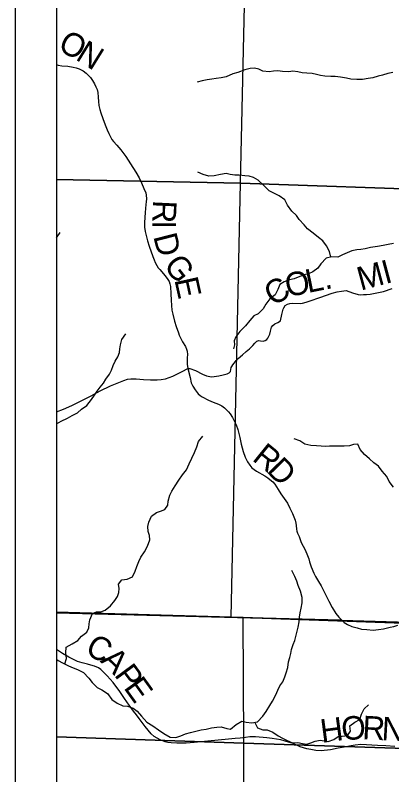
# Model space of a CAD drawing. Extents: x 0 to 34, y 0 to 22.
# Drawn here: x 2 to 2.91, y 18.326 to 20.162 of the extents above; entities that cross this region are included whole.
import ezdxf

# ---------------------------------------------------------------- set-up
doc = ezdxf.new("R2010")
doc.units = 0
for name, color, linetype in [('Default', 7, 'Continuous'), ('GM_X_County_Road', 7, 'Continuous'), ('GM_X_County_Road_Text', 7, 'Continuous'), ('GM_X_Minor_River', 7, 'Continuous'), ('GM_X_Rail_Line', 7, 'Continuous'), ('GM_X_Section', 7, 'Continuous'), ('GM_X_Township_Road', 7, 'Continuous'), ('GM_X_Township_Road_Text', 7, 'Continuous'), ('SH_Cut_Line', 7, 'Continuous'), ('SH_Data', 7, 'Continuous')]:
    doc.layers.add(name, color=color, linetype=linetype)

msp = doc.modelspace()

# ---------------------------------------------------------------- linework, layer by layer
at = {"layer": 'Default'}
for points in [[(2.1, 20.7777), (2.1, 19.7647), (2.5439, 19.7556), (2.5664, 20.7581)], [(2.1, 19.7647), (2.1, 18.7189), (2.5214, 18.7068), (2.5439, 19.7556)], [(2.1, 18.7189), (2.1, 18.418), (2.5522, 18.4023), (2.551, 18.706), (2.5214, 18.7068)], [(2.1, 18.418), (2.1, 17.4114), (2.5532, 17.3998), (2.5522, 18.4023)]]:
    msp.add_lwpolyline(points, close=True, dxfattribs=at)
at = {"layer": 'GM_X_County_Road'}
msp.add_lwpolyline([(2.9169, 18.3941), (2.8954, 18.3961), (2.8751, 18.3972), (2.8344, 18.399), (2.8213, 18.3978), (2.8112, 18.3959), (2.7948, 18.3926), (2.7799, 18.39), (2.7618, 18.3863), (2.7392, 18.3841), (2.7261, 18.3847), (2.7142, 18.3868), (2.7047, 18.3888), (2.6881, 18.3937), (2.6711, 18.4017), (2.652, 18.4071), (2.6412, 18.4102), (2.6311, 18.4122), (2.6203, 18.4141), (2.6077, 18.4157), (2.5804, 18.4178), (2.5671, 18.4178), (2.5561, 18.4162), (2.5435, 18.4145), (2.5311, 18.4134), (2.5154, 18.4121), (2.4653, 18.4076), (2.4322, 18.4043), (2.4128, 18.4023), (2.3905, 18.4023), (2.377, 18.403), (2.3688, 18.4042), (2.3623, 18.4059), (2.3505, 18.4103), (2.3428, 18.4142), (2.3355, 18.4189), (2.3283, 18.4252), (2.3213, 18.4337), (2.3136, 18.4429), (2.2991, 18.4622), (2.2927, 18.471), (2.286, 18.4798), (2.2752, 18.4943), (2.2636, 18.5108), (2.2525, 18.5272), (2.2365, 18.5492), (2.2224, 18.5654), (2.2152, 18.5727), (2.207, 18.5801), (2.2008, 18.5843), (2.1915, 18.5884), (2.183, 18.5909), (2.1747, 18.5931), (2.1621, 18.5962), (2.1505, 18.5999), (2.1292, 18.6105), (2.1141, 18.6193), (2.1018, 18.6275), (2.1, 18.6286)], dxfattribs=at)
at = {"layer": 'GM_X_Minor_River'}
for points in [[(2.912, 20.0233), (2.9002, 20.0205), (2.887, 20.017), (2.8765, 20.0139), (2.864, 20.0104), (2.8527, 20.0084), (2.8387, 20.0064), (2.8254, 20.0059), (2.8107, 20.0073), (2.8004, 20.0098), (2.786, 20.012), (2.7731, 20.0138), (2.7625, 20.0133), (2.7478, 20.0139), (2.7372, 20.0161), (2.7277, 20.0179), (2.7174, 20.0205), (2.7046, 20.0215), (2.6928, 20.0226), (2.683, 20.0244), (2.6708, 20.0262), (2.661, 20.0246), (2.6458, 20.0259), (2.6341, 20.027), (2.6239, 20.0265), (2.6137, 20.0249), (2.5985, 20.0263), (2.5883, 20.0315), (2.5776, 20.0337), (2.5674, 20.0328), (2.5546, 20.0293), (2.538, 20.0235), (2.5255, 20.0196), (2.5093, 20.0126), (2.4972, 20.0099), (2.4851, 20.0086), (2.4753, 20.007), (2.464, 20.0054), (2.4515, 20.003), (2.4398, 19.9999)], [(2.7623, 19.577), (2.7591, 19.5908), (2.7522, 19.604), (2.743, 19.6165), (2.7327, 19.6247), (2.7193, 19.6349), (2.7056, 19.6454), (2.698, 19.6551), (2.6861, 19.6676), (2.6792, 19.6774), (2.6678, 19.6879), (2.6574, 19.7022), (2.6509, 19.7158), (2.6379, 19.7248), (2.6261, 19.7307), (2.6132, 19.7371), (2.6006, 19.7499), (2.5869, 19.763), (2.5758, 19.769), (2.5652, 19.7727), (2.5546, 19.7737), (2.5406, 19.7748), (2.5307, 19.775), (2.5194, 19.7765), (2.5099, 19.7787), (2.4955, 19.777), (2.4808, 19.7731), (2.4675, 19.7726), (2.4543, 19.7763), (2.4413, 19.7822)], [(2.1, 19.6236), (2.1013, 19.6257), (2.1084, 19.6368)], [(2.9137, 19.6096), (2.9009, 19.6076), (2.8884, 19.6048), (2.8748, 19.6025), (2.8585, 19.6), (2.8453, 19.5973), (2.8351, 19.5957), (2.8253, 19.5944), (2.8132, 19.5924), (2.8019, 19.5874), (2.7909, 19.5828), (2.7789, 19.577), (2.7649, 19.5776), (2.7513, 19.5745), (2.7385, 19.5607), (2.7307, 19.5504), (2.719, 19.5416), (2.7081, 19.5362), (2.6979, 19.5338), (2.6873, 19.5299), (2.6737, 19.5249), (2.6628, 19.5221), (2.6496, 19.5171), (2.6394, 19.5106), (2.6342, 19.4991), (2.6275, 19.4862), (2.6151, 19.4762), (2.6054, 19.4636), (2.5987, 19.4522), (2.5871, 19.44), (2.5765, 19.4353), (2.5664, 19.4242), (2.5559, 19.4113), (2.5424, 19.3975), (2.5327, 19.3845), (2.529, 19.3746), (2.5298, 19.3652), (2.5269, 19.3557)], [(2.1, 19.1743), (2.1109, 19.1803), (2.126, 19.1877), (2.1377, 19.1942), (2.1501, 19.2011), (2.1599, 19.2092), (2.173, 19.2188), (2.1839, 19.2333), (2.1914, 19.2432), (2.1977, 19.2527), (2.2056, 19.2627), (2.2135, 19.2722), (2.219, 19.2821), (2.228, 19.2939), (2.2325, 19.3042), (2.2365, 19.3152), (2.2417, 19.3255), (2.2477, 19.3362), (2.2518, 19.3461), (2.2528, 19.3556), (2.2546, 19.3651), (2.2579, 19.3776), (2.2669, 19.3917)], [(2.1198, 18.5938), (2.1239, 18.6069), (2.1223, 18.6205), (2.1233, 18.6346), (2.1373, 18.6423), (2.1516, 18.6507), (2.1602, 18.661), (2.1733, 18.671), (2.1782, 18.6813), (2.1788, 18.6908), (2.1803, 18.7006), (2.1866, 18.7162), (2.1964, 18.7201), (2.207, 18.7202), (2.2172, 18.7241), (2.2299, 18.7344), (2.2408, 18.7474), (2.2468, 18.7569), (2.2505, 18.7664), (2.2515, 18.7763), (2.2492, 18.7869), (2.2578, 18.7972), (2.2703, 18.7984), (2.2834, 18.8042), (2.2894, 18.8183), (2.2934, 18.829), (2.299, 18.8412), (2.3031, 18.8518), (2.3124, 18.8652), (2.3199, 18.8789), (2.3254, 18.8941), (2.3242, 18.9039), (2.3215, 18.9138), (2.3202, 18.9262), (2.3224, 18.9369), (2.3291, 18.951), (2.3411, 18.9598), (2.3509, 18.9629), (2.3615, 18.9668), (2.369, 18.9778), (2.3696, 18.9873), (2.3737, 19.0014), (2.3785, 19.0113), (2.3863, 19.0242), (2.3949, 19.0383), (2.4043, 19.0509), (2.4136, 19.0632), (2.4203, 19.0776), (2.4263, 19.0913), (2.4329, 19.105), (2.4385, 19.1183), (2.4429, 19.1316), (2.453, 19.1442)], [(2.914, 19.0208), (2.9033, 19.0344), (2.8975, 19.0472), (2.8864, 19.0597), (2.8776, 19.0721), (2.8662, 19.0799), (2.8559, 19.0893), (2.8433, 19.1002), (2.833, 19.1123), (2.8272, 19.1247), (2.817, 19.1239), (2.8071, 19.1208), (2.7947, 19.1199), (2.7822, 19.1198), (2.772, 19.1205), (2.7595, 19.1203), (2.7493, 19.1191), (2.7386, 19.1198), (2.7277, 19.1208), (2.7137, 19.1215), (2.6996, 19.1248), (2.6871, 19.1334), (2.6738, 19.1382)], [(2.4363, 18.4314), (2.4491, 18.4346), (2.4616, 18.4366), (2.474, 18.4393), (2.4869, 18.4413), (2.4975, 18.4422), (2.5108, 18.4381), (2.5202, 18.4363), (2.5334, 18.4474), (2.5477, 18.4559), (2.5576, 18.4529), (2.5712, 18.4515), (2.5852, 18.4539), (2.5979, 18.4677), (2.6065, 18.4791), (2.6147, 18.4936), (2.6218, 18.5043), (2.6296, 18.5191), (2.6345, 18.5309), (2.6393, 18.5408), (2.6464, 18.5507), (2.6512, 18.5625), (2.6545, 18.5728), (2.6586, 18.5857), (2.6604, 18.599), (2.6633, 18.6097), (2.6659, 18.6195), (2.6677, 18.629), (2.6717, 18.6408), (2.6754, 18.6503), (2.678, 18.6602), (2.6813, 18.6731), (2.6835, 18.683), (2.6856, 18.6959), (2.687, 18.7073), (2.6885, 18.7171), (2.6906, 18.7285), (2.6928, 18.7414), (2.6934, 18.7543), (2.6891, 18.7695), (2.6833, 18.7831), (2.6806, 18.794), (2.6752, 18.8054), (2.6683, 18.8197)], [(2.1, 18.6053), (2.1039, 18.6022), (2.1142, 18.5966), (2.1286, 18.5895), (2.1404, 18.5843), (2.1507, 18.5806), (2.1651, 18.5731), (2.1781, 18.5592), (2.1858, 18.5494), (2.198, 18.537), (2.209, 18.531), (2.2231, 18.5225), (2.2335, 18.5081), (2.246, 18.4988), (2.2601, 18.4928), (2.2711, 18.4922), (2.2847, 18.4874), (2.2943, 18.4802), (2.3054, 18.4674), (2.3183, 18.4531), (2.3324, 18.4446), (2.3458, 18.4348), (2.3587, 18.4258), (2.3739, 18.4172), (2.3883, 18.4162), (2.4, 18.4201), (2.4117, 18.4248), (2.423, 18.4279), (2.4363, 18.4314)], [(2.5785, 18.4528), (2.5853, 18.4395), (2.5982, 18.4343), (2.6084, 18.4348), (2.6221, 18.4292), (2.6351, 18.4199), (2.6453, 18.4143), (2.6552, 18.4094), (2.67, 18.4035), (2.6825, 18.404), (2.6943, 18.4018), (2.7045, 18.4004), (2.7143, 18.4035), (2.7241, 18.4074), (2.7362, 18.4094), (2.7461, 18.4083), (2.7555, 18.4069), (2.7699, 18.4112), (2.7797, 18.4185), (2.7895, 18.4193), (2.8027, 18.4213), (2.8102, 18.4316), (2.8082, 18.4441), (2.8202, 18.4533), (2.8327, 18.4599), (2.8367, 18.4724), (2.843, 18.4854), (2.8536, 18.4953)]]:
    msp.add_lwpolyline(points, dxfattribs=at)
at = {"layer": 'GM_X_Rail_Line'}
for points in [[(4.5874, 20.9), (2.1, 20.9), (2.1, 18.7171), (2.7864, 18.6994), (2.7892, 18.6993), (2.9222, 18.6946), (2.9234, 18.6945), (3.8442, 18.6615), (3.8456, 18.6615), (4.5462, 18.6416), (4.5515, 18.7621), (4.5519, 18.771), (4.5566, 18.8683), (4.5569, 18.8737), (4.5569, 18.8748), (4.5571, 18.8875), (4.5772, 20.3136), (4.5773, 20.3149)], [(2.1, 18.7171), (2.1, 14.1), (4.5781, 14.1), (4.5658, 14.9668), (4.5509, 15.5331), (4.5478, 16.582), (4.5489, 17.6578), (4.5474, 17.7028), (4.5429, 17.9404), (4.5419, 17.9684), (4.5402, 18.2851), (4.5408, 18.3763), (4.5397, 18.3961), (4.5397, 18.4045), (4.5399, 18.4424), (4.5403, 18.5054), (4.5462, 18.6416), (3.8456, 18.6615), (3.8442, 18.6615), (2.9234, 18.6945), (2.9222, 18.6946), (2.7892, 18.6993), (2.7864, 18.6994)]]:
    msp.add_lwpolyline(points, close=True, dxfattribs=at)
at = {"layer": 'GM_X_Section'}
for points in [[(2.5664, 20.7581), (3.5738, 20.7275), (3.5637, 19.7201), (2.5439, 19.7556)], [(2.5439, 19.7556), (3.5637, 19.7201), (3.5541, 18.6711), (2.551, 18.706), (2.5214, 18.7068)], [(2.551, 18.706), (3.5541, 18.6711), (3.5508, 18.3698), (2.5522, 18.4023)], [(2.5522, 18.4023), (3.5508, 18.3698), (3.5573, 17.3676), (2.5532, 17.3998)]]:
    msp.add_lwpolyline(points, close=True, dxfattribs=at)
at = {"layer": 'GM_X_Township_Road'}
for points in [[(2.1, 20.0421), (2.1041, 20.0411), (2.1126, 20.0396), (2.1268, 20.0382), (2.1398, 20.0362), (2.1469, 20.0347), (2.1548, 20.0318), (2.1644, 20.0268), (2.1717, 20.0212), (2.1774, 20.0159), (2.1821, 20.0107), (2.1871, 20.0034), (2.1916, 19.9955), (2.1951, 19.9882), (2.1976, 19.9818), (2.1996, 19.9745), (2.2006, 19.9634), (2.2014, 19.9528), (2.202, 19.9435), (2.2044, 19.9337), (2.2068, 19.9254), (2.2116, 19.9119), (2.2172, 19.8963), (2.2218, 19.8846), (2.2258, 19.8758), (2.2298, 19.868), (2.2336, 19.8616), (2.2377, 19.8565), (2.2455, 19.8472), (2.2548, 19.8364), (2.2674, 19.8203), (2.2782, 19.8025), (2.2911, 19.7821), (2.2993, 19.7684), (2.3049, 19.7564), (2.3109, 19.7429), (2.3152, 19.7322), (2.3164, 19.7266), (2.3168, 19.7179), (2.3167, 19.7109), (2.3158, 19.7039), (2.3138, 19.6845), (2.3122, 19.6605), (2.312, 19.6496), (2.3136, 19.6387), (2.3168, 19.6259), (2.3193, 19.6166), (2.3234, 19.6037), (2.3323, 19.5783), (2.3355, 19.5703), (2.3383, 19.5641), (2.342, 19.5564), (2.3453, 19.5513), (2.349, 19.5469), (2.3621, 19.5317), (2.3685, 19.5232), (2.3718, 19.5178), (2.3736, 19.5126), (2.3752, 19.5058), (2.3759, 19.4884), (2.3765, 19.4726), (2.3773, 19.4602), (2.3786, 19.4486), (2.3806, 19.439), (2.385, 19.4223), (2.3887, 19.4091), (2.3941, 19.3939), (2.3962, 19.3885), (2.3985, 19.3835), (2.4042, 19.3726), (2.411, 19.3611), (2.414, 19.3545), (2.4154, 19.3496), (2.416, 19.342), (2.4157, 19.3335), (2.4156, 19.3183), (2.4171, 19.3075), (2.4223, 19.2863), (2.4252, 19.2735), (2.4289, 19.2654), (2.4346, 19.2559), (2.4417, 19.2467), (2.4469, 19.2423), (2.4517, 19.2393), (2.4669, 19.2314), (2.4782, 19.2267), (2.4914, 19.2215), (2.4987, 19.2173), (2.5054, 19.2126), (2.5103, 19.2082), (2.5153, 19.2028), (2.5189, 19.1979), (2.5247, 19.1894), (2.5282, 19.1826), (2.5339, 19.1714), (2.5379, 19.1606), (2.5427, 19.1414), (2.5459, 19.1251), (2.5507, 19.107), (2.5557, 19.0937), (2.5614, 19.0822), (2.5666, 19.074), (2.5718, 19.068), (2.5771, 19.0635), (2.5829, 19.0599), (2.6027, 19.0482), (2.6099, 19.0439), (2.6153, 19.0399), (2.6223, 19.0337), (2.6271, 19.0282), (2.6348, 19.0154), (2.6414, 19.0053), (2.6576, 18.9828), (2.6637, 18.97), (2.6695, 18.9574), (2.6732, 18.9498), (2.6762, 18.9411), (2.6779, 18.9343), (2.6787, 18.9281), (2.6794, 18.9199), (2.6803, 18.915), (2.6819, 18.91), (2.6858, 18.9017), (2.691, 18.8876), (2.7001, 18.8699), (2.7063, 18.8557), (2.709, 18.8482), (2.7112, 18.8408), (2.7148, 18.8284), (2.7213, 18.813), (2.7255, 18.805), (2.7323, 18.7931), (2.7387, 18.7826), (2.7574, 18.7453), (2.7656, 18.7301), (2.7747, 18.7159), (2.7819, 18.7071), (2.7894, 18.6988), (2.7925, 18.6961)], [(2.1, 19.2035), (2.1163, 19.2096), (2.1365, 19.2182), (2.1832, 19.2418), (2.2054, 19.2541), (2.2305, 19.2659), (2.2625, 19.279), (2.2712, 19.2822), (2.2792, 19.2831), (2.2925, 19.2827), (2.3099, 19.281), (2.3271, 19.2803), (2.3428, 19.2808), (2.3524, 19.2814), (2.3628, 19.2832), (2.3807, 19.2894), (2.3953, 19.2967), (2.4035, 19.3008), (2.4171, 19.3075), (2.4194, 19.308), (2.422, 19.308), (2.4353, 19.3031), (2.4522, 19.2942), (2.462, 19.2905), (2.47, 19.2884), (2.4747, 19.2878), (2.4919, 19.2905), (2.5026, 19.2922), (2.5117, 19.2951), (2.5164, 19.2974), (2.5198, 19.3006), (2.522, 19.3099), (2.5231, 19.3129), (2.5255, 19.3169), (2.5286, 19.321), (2.5337, 19.3272), (2.5388, 19.3324), (2.5493, 19.3406), (2.5582, 19.349), (2.5655, 19.3557), (2.5742, 19.3636), (2.579, 19.3688), (2.5839, 19.3742), (2.5881, 19.3757), (2.5923, 19.375), (2.5986, 19.3737), (2.6035, 19.3756), (2.6076, 19.3783), (2.6101, 19.381), (2.6151, 19.3904), (2.6165, 19.3982), (2.6187, 19.4076), (2.6224, 19.4119), (2.6271, 19.4155), (2.6341, 19.4186), (2.6409, 19.4228), (2.6443, 19.4386), (2.6472, 19.451), (2.6491, 19.4543), (2.6524, 19.4602), (2.6579, 19.463), (2.6633, 19.4648), (2.6694, 19.4657), (2.688, 19.4651), (2.6942, 19.4656), (2.7027, 19.4681), (2.7127, 19.4717), (2.7354, 19.4794), (2.7655, 19.4896), (2.7779, 19.4928), (2.7883, 19.4945), (2.7997, 19.4962), (2.8143, 19.491), (2.8284, 19.4866), (2.8346, 19.4862), (2.8415, 19.4868), (2.8482, 19.4864), (2.8573, 19.4875), (2.8815, 19.4923), (2.8892, 19.4938), (2.9104, 19.5011)], [(2.7925, 18.6961), (2.7949, 18.6941), (2.8027, 18.6892), (2.8133, 18.6847), (2.8258, 18.6808), (2.8362, 18.6783), (2.8496, 18.6769), (2.8646, 18.6758), (2.8777, 18.6771), (2.8893, 18.6789), (2.9056, 18.6825), (2.9145, 18.6846), (2.9242, 18.6876)]]:
    msp.add_lwpolyline(points, dxfattribs=at)
at = {"layer": 'SH_Cut_Line'}
msp.add_lwpolyline([(8.9, 14.624), (8.9, 20.9), (2.1, 20.9), (2.1, 14.1)], dxfattribs=at)
at = {"layer": 'SH_Data'}
for p, q in [((2, 21), (2, 14)), ((2.1, 20.9), (2.1, 14.1))]:
    msp.add_line(p, q, dxfattribs=at)

# ---------------------------------------------------------------- texts
at = {"layer": 'GM_X_County_Road_Text'}
for s, rotation, p in [('C', 330.884, (2.166, 18.6205)), ('A', 315.7599, (2.2036, 18.6001)), ('P', 306.5192, (2.2378, 18.5671)), ('E', 305.7908, (2.2605, 18.5364)), ('O', 3.3314, (2.7892, 18.4094)), ('R', 356.9152, (2.8374, 18.4123)), ('N', 356.7709, (2.884, 18.4098)), ('H', 7.5222, (2.7407, 18.403))]:
    msp.add_text(s, height=0.0568, rotation=rotation, dxfattribs=at).set_placement(p)
at = {"layer": 'GM_X_Township_Road_Text'}
for s, rotation, p in [('O', 331.302, (2.1004, 20.0791)), ('N', 328.1784, (2.1435, 20.0555)), ('R', 267.3567, (2.3335, 19.7154)), ('I', 269.9931, (2.3313, 19.6659)), ('D', 284.2584, (2.3332, 19.6273)), ('G', 307.693, (2.3566, 19.5562)), ('I', 14.9545, (2.894, 19.5118)), ('M', 15.1295, (2.8345, 19.4957)), ('O', 12.1001, (2.6583, 19.4797)), ('L', 11.4587, (2.7071, 19.4901)), ('E', 282.427, (2.3843, 19.5225)), ('C', 31.5983, (2.6233, 19.4571)), ('.', 10.0647, (2.7484, 19.4985)), ('R', 321.0744, (2.5702, 19.0874)), ('D', 314.3354, (2.6052, 19.0593))]:
    msp.add_text(s, height=0.0568, rotation=rotation, dxfattribs=at).set_placement(p)

doc.saveas('drawing.dxf')
